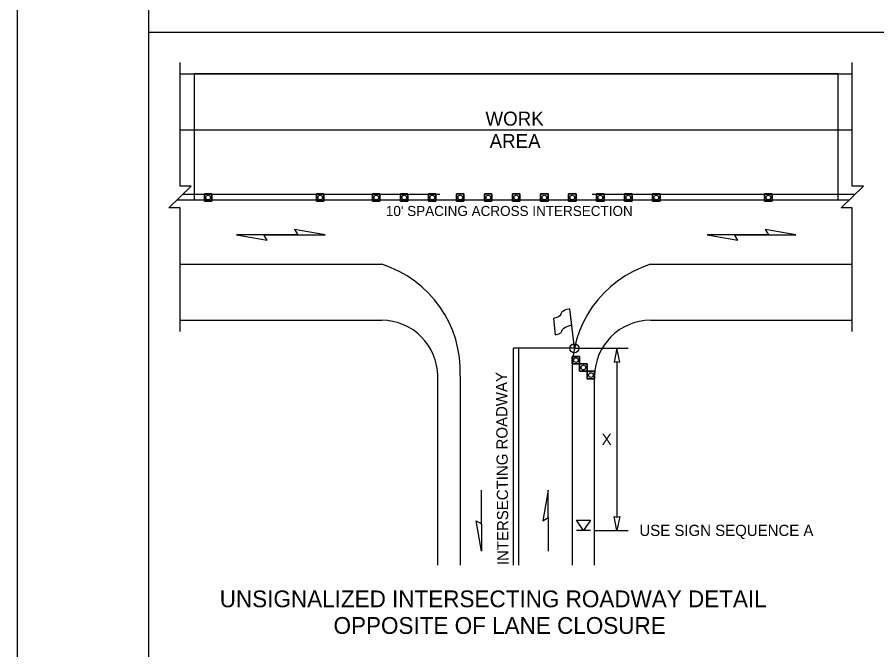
# Model space of a CAD drawing. Extents: x 99999.1 to 100095.7, y 99995 to 100010.7.
# Drawn here: x 100019.06 to 100025.2, y 100001.57 to 100006.09 of the extents above; entities that cross this region are included whole.
import ezdxf

# ---------------------------------------------------------------- set-up
doc = ezdxf.new("R2010")
doc.units = 0
for name, color, linetype in [('RD_ED_ShoulderPavedEdge', 7, 'Continuous'), ('RD_MK_LineDblYellowCenter', 7, 'Continuous'), ('RD_MK_LineEdgeWhite', 7, 'Continuous'), ('RD_MK_LineStop', 7, 'Continuous'), ('SH_DE_DetailBody1Text', 7, 'Continuous'), ('SH_DE_DetailHeading2Text', 7, 'Continuous'), ('SH_GI_PlotLimits', 7, 'Continuous'), ('SH_GI_SheetBorder', 7, 'Continuous'), ('TR_WZ_FlaggingStation', 7, 'Continuous'), ('TR_WZ_PortableSignMountBlk-Org', 7, 'Continuous'), ('TR_WZ_TrafficCone', 7, 'Continuous'), ('TR_WZ_WorkAreaLabel', 7, 'Continuous'), ('TR_WZ_WorkZoneDetails', 7, 'Continuous'), ('TR_WZ_WorkZoneTextCurrent', 7, 'Continuous')]:
    doc.layers.add(name, color=color, linetype=linetype)

msp = doc.modelspace()

# ---------------------------------------------------------------- linework, layer by layer
at = {"layer": 'RD_ED_ShoulderPavedEdge'}
for p, q in [((100020.225, 100005.6849), (100025.025, 100005.6849)), ((100020.225, 100003.9249), (100021.665, 100003.9249)), ((100023.585, 100003.9249), (100025.025, 100003.9249))]:
    msp.add_line(p, q, dxfattribs=at)
for points in [[(100022.065, 100002.1759), (100022.065, 100003.5249)], [(100023.185, 100002.1759), (100023.185, 100003.5249)]]:
    msp.add_lwpolyline(points, dxfattribs=at)
for centre, start, end in [((100021.665, 100003.5249), 0, 90), ((100023.585, 100003.5249), 90, 180)]:
    msp.add_arc(centre, 0.4, start, end, dxfattribs=at)
at = {"layer": 'RD_MK_LineDblYellowCenter'}
for p, q in [((100020.2457, 100004.8249), (100022.0812, 100004.8249)), ((100023.1688, 100004.8249), (100025.0457, 100004.8249)), ((100020.2043, 100004.7849), (100022.0812, 100004.7849)), ((100023.1688, 100004.7849), (100025.0043, 100004.7849)), ((100022.605, 100002.1759), (100022.605, 100003.7249)), ((100022.645, 100002.1759), (100022.645, 100003.7249))]:
    msp.add_line(p, q, dxfattribs=at)
at = {"layer": 'RD_MK_LineEdgeWhite'}
for p, q in [((100020.225, 100005.2849), (100025.025, 100005.2849)), ((100020.225, 100004.3249), (100021.665, 100004.3249)), ((100023.585, 100004.3249), (100025.025, 100004.3249)), ((100022.225, 100003.5249), (100022.225, 100002.1759)), ((100023.025, 100003.5249), (100023.025, 100002.1759))]:
    msp.add_line(p, q, dxfattribs=at)
for centre, start, end in [((100021.4258, 100003.5615), 357.37881, 72.60523), ((100023.8242, 100003.5615), 107.39477, 182.62119)]:
    msp.add_arc(centre, 0.8, start, end, dxfattribs=at)
at = {"layer": 'RD_MK_LineStop'}
msp.add_line((100023.041, 100003.7249), (100022.605, 100003.7249), dxfattribs=at)
at = {"layer": 'SH_GI_PlotLimits'}
msp.add_lwpolyline([(100019.0625, 99999.6875), (100036.0625, 99999.6875), (100036.0625, 100010.6875), (100019.0625, 100010.6875)], close=True, dxfattribs=at)
at = {"layer": 'SH_GI_SheetBorder'}
msp.add_line((100020, 100010.375), (100020, 100000), dxfattribs=at)
at = {"layer": 'TR_WZ_FlaggingStation'}
for p, q in [((100023.022, 100003.8918), (100023.0089, 100004.0062)), ((100023.041, 100003.7249), (100023.009, 100004.0059)), ((100022.891, 100003.9384), (100022.9043, 100003.8212)), ((100023.022, 100003.8918), (100023.022, 100003.8918))]:
    msp.add_line(p, q, dxfattribs=at)
for points in [[(100023.0089, 100004.0062), (100023.0032, 100004.0049), (100022.9854, 100004.0015), (100022.9715, 100003.9973), (100022.9619, 100003.9912), (100022.9533, 100003.9865), (100022.9477, 100003.9797), (100022.9434, 100003.9718), (100022.9429, 100003.9656), (100022.9375, 100003.9564), (100022.9267, 100003.949), (100022.9143, 100003.9438), (100022.891, 100003.9384)], [(100022.9043, 100003.8212), (100022.9124, 100003.8226), (100022.9301, 100003.8272), (100022.9458, 100003.8377), (100022.9523, 100003.8483), (100022.9562, 100003.8586), (100022.9653, 100003.8695), (100022.9763, 100003.8757), (100022.9936, 100003.8828), (100023.022, 100003.8918)]]:
    msp.add_lwpolyline(points, dxfattribs=at)
msp.add_circle((100023.041, 100003.7249), 0.0325, dxfattribs=at)
at = {"layer": 'TR_WZ_PortableSignMountBlk-Org'}
msp.add_line((100023.1549, 100002.4249), (100023.0549, 100002.4249), dxfattribs=at)
msp.add_lwpolyline([(100023.105, 100002.4249), (100023.0549, 100002.4968), (100023.1549, 100002.4968)], close=True, dxfattribs=at)
at = {"layer": 'TR_WZ_TrafficCone'}
for points in [[(100020.399, 100004.8283), (100020.4524, 100004.8283), (100020.4524, 100004.7749), (100020.399, 100004.7749), (100020.399, 100004.8283)], [(100020.399, 100004.7749), (100020.4524, 100004.7749), (100020.4524, 100004.8283), (100020.399, 100004.8283), (100020.399, 100004.7749)], [(100021.199, 100004.8283), (100021.2524, 100004.8283), (100021.2524, 100004.7749), (100021.199, 100004.7749), (100021.199, 100004.8283)], [(100021.199, 100004.7749), (100021.2524, 100004.7749), (100021.2524, 100004.8283), (100021.199, 100004.8283), (100021.199, 100004.7749)], [(100021.599, 100004.8283), (100021.6524, 100004.8283), (100021.6524, 100004.7749), (100021.599, 100004.7749), (100021.599, 100004.8283)], [(100021.599, 100004.7749), (100021.6524, 100004.7749), (100021.6524, 100004.8283), (100021.599, 100004.8283), (100021.599, 100004.7749)], [(100021.799, 100004.8283), (100021.8524, 100004.8283), (100021.8524, 100004.7749), (100021.799, 100004.7749), (100021.799, 100004.8283)], [(100021.799, 100004.7749), (100021.8524, 100004.7749), (100021.8524, 100004.8283), (100021.799, 100004.8283), (100021.799, 100004.7749)], [(100021.999, 100004.8283), (100022.0524, 100004.8283), (100022.0524, 100004.7749), (100021.999, 100004.7749), (100021.999, 100004.8283)], [(100021.999, 100004.7749), (100022.0524, 100004.7749), (100022.0524, 100004.8283), (100021.999, 100004.8283), (100021.999, 100004.7749)], [(100022.199, 100004.8283), (100022.2524, 100004.8283), (100022.2524, 100004.7749), (100022.199, 100004.7749), (100022.199, 100004.8283)], [(100022.199, 100004.7749), (100022.2524, 100004.7749), (100022.2524, 100004.8283), (100022.199, 100004.8283), (100022.199, 100004.7749)], [(100022.399, 100004.8283), (100022.4524, 100004.8283), (100022.4524, 100004.7749), (100022.399, 100004.7749), (100022.399, 100004.8283)], [(100022.399, 100004.7749), (100022.4524, 100004.7749), (100022.4524, 100004.8283), (100022.399, 100004.8283), (100022.399, 100004.7749)], [(100022.599, 100004.8283), (100022.6524, 100004.8283), (100022.6524, 100004.7749), (100022.599, 100004.7749), (100022.599, 100004.8283)], [(100022.599, 100004.7749), (100022.6524, 100004.7749), (100022.6524, 100004.8283), (100022.599, 100004.8283), (100022.599, 100004.7749)], [(100022.799, 100004.8283), (100022.8524, 100004.8283), (100022.8524, 100004.7749), (100022.799, 100004.7749), (100022.799, 100004.8283)], [(100022.799, 100004.7749), (100022.8524, 100004.7749), (100022.8524, 100004.8283), (100022.799, 100004.8283), (100022.799, 100004.7749)], [(100022.999, 100004.8283), (100023.0524, 100004.8283), (100023.0524, 100004.7749), (100022.999, 100004.7749), (100022.999, 100004.8283)], [(100022.999, 100004.7749), (100023.0524, 100004.7749), (100023.0524, 100004.8283), (100022.999, 100004.8283), (100022.999, 100004.7749)], [(100023.199, 100004.8283), (100023.2524, 100004.8283), (100023.2524, 100004.7749), (100023.199, 100004.7749), (100023.199, 100004.8283)], [(100023.199, 100004.7749), (100023.2524, 100004.7749), (100023.2524, 100004.8283), (100023.199, 100004.8283), (100023.199, 100004.7749)], [(100023.399, 100004.8283), (100023.4524, 100004.8283), (100023.4524, 100004.7749), (100023.399, 100004.7749), (100023.399, 100004.8283)], [(100023.399, 100004.7749), (100023.4524, 100004.7749), (100023.4524, 100004.8283), (100023.399, 100004.8283), (100023.399, 100004.7749)], [(100023.599, 100004.8283), (100023.6524, 100004.8283), (100023.6524, 100004.7749), (100023.599, 100004.7749), (100023.599, 100004.8283)], [(100023.599, 100004.7749), (100023.6524, 100004.7749), (100023.6524, 100004.8283), (100023.599, 100004.8283), (100023.599, 100004.7749)], [(100024.399, 100004.8283), (100024.4524, 100004.8283), (100024.4524, 100004.7749), (100024.399, 100004.7749), (100024.399, 100004.8283)], [(100024.399, 100004.7749), (100024.4524, 100004.7749), (100024.4524, 100004.8283), (100024.399, 100004.8283), (100024.399, 100004.7749)], [(100023.025, 100003.6142), (100023.025, 100003.6676), (100023.0783, 100003.6676), (100023.0783, 100003.6142), (100023.025, 100003.6142)], [(100023.0783, 100003.6142), (100023.0783, 100003.6676), (100023.025, 100003.6676), (100023.025, 100003.6142), (100023.0783, 100003.6142)], [(100023.0783, 100003.5609), (100023.0783, 100003.6142), (100023.1317, 100003.6142), (100023.1317, 100003.5609), (100023.0783, 100003.5609)], [(100023.1317, 100003.5609), (100023.1317, 100003.6142), (100023.0783, 100003.6142), (100023.0783, 100003.5609), (100023.1317, 100003.5609)], [(100023.1317, 100003.5076), (100023.1317, 100003.5609), (100023.185, 100003.5609), (100023.185, 100003.5076), (100023.1317, 100003.5076)], [(100023.185, 100003.5076), (100023.185, 100003.5609), (100023.1317, 100003.5609), (100023.1317, 100003.5076), (100023.185, 100003.5076)]]:
    msp.add_lwpolyline(points, dxfattribs=at)
for centre in [(100020.4257, 100004.8016), (100021.2257, 100004.8016), (100021.6257, 100004.8016), (100021.8257, 100004.8016), (100022.0257, 100004.8016), (100022.2257, 100004.8016), (100022.4257, 100004.8016), (100022.6257, 100004.8016), (100022.8257, 100004.8016), (100023.0257, 100004.8016), (100023.2257, 100004.8016), (100023.4257, 100004.8016), (100023.6257, 100004.8016), (100024.4257, 100004.8016), (100023.0517, 100003.6409), (100023.105, 100003.5876), (100023.1583, 100003.5342)]:
    msp.add_circle(centre, 0.0167, dxfattribs=at)
at = {"layer": 'TR_WZ_WorkZoneDetails'}
for p, q in [((100025.25, 100005.9805), (100020, 100005.9805)), ((100020.8244, 100004.5349), (100021.0656, 100004.5349)), ((100021.0656, 100004.5349), (100020.8244, 100004.5349)), ((100024.1844, 100004.5349), (100024.4256, 100004.5349)), ((100024.4256, 100004.5349), (100024.1844, 100004.5349)), ((100023.041, 100003.7249), (100023.425, 100003.7249)), ((100023.345, 100003.6312), (100023.345, 100002.5187)), ((100022.3772, 100002.4718), (100022.3772, 100002.7129)), ((100022.8545, 100002.5164), (100022.8545, 100002.2753)), ((100023.185, 100002.4249), (100023.425, 100002.4249))]:
    msp.add_line(p, q, dxfattribs=at)
for points in [[(100020.225, 100003.8449), (100020.225, 100004.7275), (100020.145, 100004.7275), (100020.305, 100004.8824), (100020.225, 100004.8824), (100020.225, 100005.7649)], [(100025.025, 100003.8449), (100025.025, 100004.7275), (100024.945, 100004.7275), (100025.105, 100004.8824), (100025.025, 100004.8824), (100025.025, 100005.7649)]]:
    msp.add_lwpolyline(points, dxfattribs=at)
for points in [[(100020.325, 100005.6849), (100020.325, 100004.7849), (100024.925, 100004.7849), (100024.925, 100005.6849)], [(100021.2621, 100004.5349), (100021.0433, 100004.5735), (100021.0656, 100004.5349)], [(100024.6221, 100004.5349), (100024.4033, 100004.5735), (100024.4256, 100004.5349)], [(100020.6279, 100004.5349), (100020.8467, 100004.4964), (100020.8244, 100004.5349)], [(100023.9879, 100004.5349), (100024.2067, 100004.4964), (100024.1844, 100004.5349)], [(100023.345, 100003.7249), (100023.3257, 100003.6266), (100023.345, 100003.6312), (100023.3643, 100003.6266)], [(100022.8545, 100002.7129), (100022.816, 100002.4941), (100022.8545, 100002.5164)], [(100023.345, 100002.4249), (100023.3257, 100002.5232), (100023.345, 100002.5187), (100023.3643, 100002.5232)], [(100022.3772, 100002.2753), (100022.3387, 100002.4941), (100022.3772, 100002.4718)]]:
    msp.add_lwpolyline(points, close=True, dxfattribs=at)

# ---------------------------------------------------------------- texts
at = {"layer": 'SH_DE_DetailBody1Text'}
msp.add_text('INTERSECTING ROADWAY', height=0.08, rotation=90.4626, dxfattribs=at).set_placement((100022.5709, 100002.1769))
at = {"layer": 'SH_DE_DetailHeading2Text'}
for s, p in [('UNSIGNALIZED INTERSECTING ROADWAY DETAIL', (100020.5086, 100001.8759)), ('OPPOSITE OF LANE CLOSURE', (100021.3211, 100001.6859))]:
    msp.add_text(s, height=0.12, rotation=360, dxfattribs=at).set_placement(p)
at = {"layer": 'TR_WZ_WorkAreaLabel'}
for s, p in [('WORK', (100022.4058, 100005.3149)), ('AREA', (100022.4354, 100005.1549))]:
    msp.add_text(s, height=0.1, dxfattribs=at).set_placement(p)
at = {"layer": 'TR_WZ_WorkZoneTextCurrent'}
for s, height, p in [("10' SPACING ACROSS INTERSECTION", 0.072, (100021.6948, 100004.6696)), ('X', 0.08, (100023.2356, 100003.0349)), ('USE SIGN SEQUENCE A', 0.08, (100023.505, 100002.3849))]:
    msp.add_text(s, height=height, dxfattribs=at).set_placement(p)

doc.saveas('drawing.dxf')
